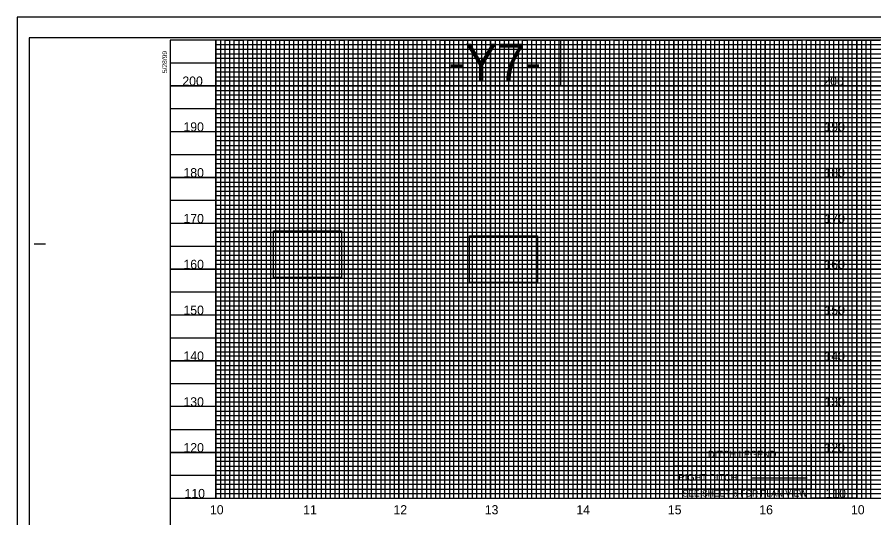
# Model space of a CAD drawing. Extents: x 1779926 to 1781626, y 618464 to 619564.
# Drawn here: x 1779926 to 1780862, y 619018 to 619564 of the extents above; entities that cross this region are included whole.
import ezdxf

# ---------------------------------------------------------------- set-up
doc = ezdxf.new("R2010")
doc.units = 0
for name, color, linetype in [('Exist Vertical Profile Horizontal Axis Label Major', 7, 'Continuous'), ('Exist Vertical Profile Vertical Axis Label', 7, 'Continuous'), ('Prop DSN Text', 7, 'Continuous'), ('Prop Grid Mask', 7, 'Continuous'), ('Prop PFL Ditch Label CELL', 7, 'Continuous'), ('Sheet DOT Grid CELL', 7, 'Continuous'), ('Sheet Layout Profile Border Port 1', 7, 'Continuous'), ('Sheet Plot Border Inside CELL', 7, 'Continuous'), ('Sheet Plot Border Outside CELL', 7, 'Continuous'), ('Sheet Profile CELL', 7, 'Continuous'), ('Sheet Profile Grid Major CELL', 7, 'Continuous'), ('Sheet Profile Grid Middle CELL', 7, 'Continuous'), ('Sheet Profile Grid Minor CELL', 7, 'Continuous')]:
    doc.layers.add(name, color=color, linetype=linetype)

msp = doc.modelspace()

# ---------------------------------------------------------------- linework, layer by layer
at = {"layer": 'Prop Grid Mask'}
for points in [[(1780519.62, 619539.19), (1780392.96, 619539.19), (1780392.96, 619489.19), (1780519.62, 619489.19)], [(1780792.96, 619539.19), (1780842.96, 619539.19), (1780842.96, 619039.19), (1780792.96, 619039.19)], [(1780205.9, 619330.88), (1780280.15, 619330.88), (1780280.15, 619279.97), (1780205.9, 619279.97)], [(1780420.08, 619325.67), (1780494.33, 619325.67), (1780494.33, 619274.76), (1780420.08, 619274.76)], [(1780642.96, 619099.19), (1780792.96, 619099.19), (1780792.96, 619074.19), (1780642.96, 619074.19)], [(1780642.96, 619074.19), (1780792.96, 619074.19), (1780792.96, 619049.19), (1780642.96, 619049.19)], [(1780792.96, 619049.19), (1780647.96, 619049.19), (1780647.96, 619039.19), (1780792.96, 619039.19)]]:
    msp.add_lwpolyline(points, close=True, dxfattribs=at)
at = {"layer": 'Prop PFL Ditch Label CELL'}
for p, q in [((1780642.96, 619059.19), (1780642.96, 619059.19)), ((1780728.51, 619061.54), (1780788.51, 619061.54)), ((1780728.51, 619061.54), (1780788.51, 619061.54))]:
    msp.add_line(p, q, dxfattribs=at)
at = {"layer": 'Sheet DOT Grid CELL'}
for p, q in [((1780142.96, 619039.19), (1780142.96, 619539.19)), ((1780192.96, 619039.19), (1780192.96, 619539.19)), ((1780242.96, 619039.19), (1780242.96, 619539.19)), ((1780292.96, 619039.19), (1780292.96, 619539.19)), ((1780342.96, 619039.19), (1780342.96, 619539.19)), ((1780392.96, 619039.19), (1780392.96, 619539.19)), ((1780442.96, 619039.19), (1780442.96, 619539.19)), ((1780492.96, 619039.19), (1780492.96, 619539.19)), ((1780542.96, 619039.19), (1780542.96, 619539.19)), ((1780592.96, 619039.19), (1780592.96, 619539.19)), ((1780642.96, 619039.19), (1780642.96, 619539.19)), ((1780692.96, 619039.19), (1780692.96, 619539.19)), ((1780742.96, 619039.19), (1780742.96, 619539.19)), ((1780792.96, 619039.19), (1780792.96, 619539.19)), ((1780842.96, 619039.19), (1780842.96, 619539.19)), ((1781392.91, 619489.19), (1780092.96, 619489.19)), ((1781392.91, 619439.19), (1780092.96, 619439.19)), ((1781392.96, 619389.19), (1780092.96, 619389.19)), ((1781392.91, 619339.19), (1780092.96, 619339.19)), ((1781592.96, 619289.19), (1780092.96, 619289.19)), ((1781592.96, 619239.19), (1780092.96, 619239.19)), ((1781592.96, 619189.19), (1780092.96, 619189.19)), ((1781592.96, 619139.19), (1780092.96, 619139.19)), ((1781592.96, 619089.19), (1780092.96, 619089.19))]:
    msp.add_line(p, q, dxfattribs=at)
at = {"layer": 'Sheet Layout Profile Border Port 1'}
for points in [[(1781542.96, 619099.19), (1781542.96, 619314.19), (1781392.91, 619314.19), (1781392.96, 619539.19), (1780142.96, 619539.19), (1780142.96, 619039.19), (1781542.96, 619039.19), (1781542.96, 619049.19)], [(1780142.96, 619378.14), (1780142.96, 619039.19), (1781542.96, 619039.19), (1781542.96, 619314.19)]]:
    msp.add_lwpolyline(points, dxfattribs=at)
at = {"layer": 'Sheet Plot Border Inside CELL'}
msp.add_lwpolyline([(1779938.96, 618486.64), (1781605.46, 618486.64), (1781605.46, 619541.74), (1779938.96, 619541.74)], close=True, dxfattribs=at)
at = {"layer": 'Sheet Plot Border Outside CELL'}
msp.add_lwpolyline([(1779925.96, 618464.19), (1781625.96, 618464.19), (1781625.96, 619564.19), (1779925.96, 619564.19)], close=True, dxfattribs=at)
at = {"layer": 'Sheet Profile CELL'}
for p, q in [((1779944.46, 619316.69), (1779956.96, 619316.69)), ((1780092.96, 619039.19), (1781592.96, 619039.19))]:
    msp.add_line(p, q, dxfattribs=at)
msp.add_lwpolyline([(1781592.96, 619539.19), (1780092.96, 619539.19), (1780092.96, 618489.19), (1781592.96, 618489.19)], close=True, dxfattribs=at)
at = {"layer": 'Sheet Profile Grid Major CELL'}
for points in [[(1780142.96, 619539.19), (1780142.96, 619039.19), (1780192.96, 619039.19), (1780192.96, 619539.19), (1780242.96, 619539.19), (1780242.96, 619039.19), (1780292.96, 619039.19), (1780292.96, 619539.19), (1780342.96, 619539.19), (1780342.96, 619039.19), (1780392.96, 619039.19), (1780392.96, 619539.19), (1780442.96, 619539.19), (1780442.96, 619039.19), (1780492.96, 619039.19), (1780492.96, 619539.19), (1780542.96, 619539.19), (1780542.96, 619039.19), (1780592.96, 619039.19), (1780592.96, 619539.19), (1780642.96, 619539.19), (1780642.96, 619039.19), (1780692.96, 619039.19), (1780692.96, 619539.19), (1780742.96, 619539.19), (1780742.96, 619039.19), (1780792.96, 619039.19), (1780792.96, 619539.19), (1780842.96, 619539.19), (1780842.96, 619039.19), (1780892.96, 619039.19)], [(1780092.96, 619489.19), (1781392.96, 619489.19)], [(1781392.96, 619439.19), (1780092.96, 619439.19), (1780092.96, 619389.19), (1781392.96, 619389.19)], [(1781392.96, 619339.19), (1780092.96, 619339.19), (1780092.96, 619289.19), (1781592.96, 619289.19)], [(1781592.96, 619239.19), (1780092.96, 619239.19), (1780092.96, 619189.19), (1781592.96, 619189.19)], [(1781592.96, 619139.19), (1780092.96, 619139.19), (1780092.96, 619139.19), (1780092.96, 619089.19), (1781592.96, 619089.19)]]:
    msp.add_lwpolyline(points, dxfattribs=at)
at = {"layer": 'Sheet Profile Grid Middle CELL'}
msp.add_line((1780092.96, 619514.19), (1781392.91, 619514.19), dxfattribs=at)
for points in [[(1780167.96, 619539.19), (1780167.96, 619039.19), (1780217.96, 619039.19), (1780217.96, 619539.19), (1780267.96, 619539.19), (1780267.96, 619039.19), (1780317.96, 619039.19), (1780317.96, 619539.19), (1780367.96, 619539.19), (1780367.96, 619039.19), (1780417.96, 619039.19), (1780417.96, 619539.19), (1780467.96, 619539.19), (1780467.96, 619039.19), (1780517.96, 619039.19), (1780517.96, 619539.19), (1780567.96, 619539.19), (1780567.96, 619039.19), (1780617.96, 619039.19), (1780617.96, 619539.19), (1780667.96, 619539.19), (1780667.96, 619039.19), (1780717.96, 619039.19), (1780717.96, 619039.19), (1780717.96, 619539.19), (1780767.96, 619539.19), (1780767.96, 619039.19), (1780817.96, 619039.19), (1780817.96, 619539.19), (1780867.96, 619539.19)], [(1781392.96, 619464.19), (1780092.96, 619464.19), (1780092.96, 619414.19), (1781392.96, 619414.19)], [(1781392.91, 619364.19), (1780092.96, 619364.19), (1780092.96, 619314.19), (1781417.96, 619314.19)], [(1781592.96, 619264.19), (1780092.96, 619264.19), (1780092.96, 619214.19), (1781592.96, 619214.19)], [(1781592.96, 619164.19), (1780092.96, 619164.19), (1780092.96, 619114.19), (1781592.96, 619114.19)], [(1781592.96, 619064.19), (1780092.96, 619064.19)]]:
    msp.add_lwpolyline(points, dxfattribs=at)
at = {"layer": 'Sheet Profile Grid Minor CELL'}
for p, q in [((1780142.96, 619534.19), (1781392.96, 619534.19)), ((1780142.96, 619529.19), (1780142.96, 619529.19)), ((1781392.96, 619529.19), (1780142.96, 619528.84)), ((1780142.96, 619524.19), (1781392.96, 619524.19)), ((1781392.91, 619404.19), (1780142.96, 619404.19)), ((1781392.96, 619399.19), (1780142.96, 619399.19)), ((1781392.96, 619394.19), (1780142.96, 619394.19)), ((1780142.96, 619384.19), (1781392.96, 619384.19)), ((1781392.96, 619379.19), (1780142.96, 619379.19)), ((1780142.96, 619374.19), (1781392.91, 619374.19)), ((1781392.91, 619354.19), (1780142.96, 619354.19)), ((1780142.96, 619349.19), (1781392.91, 619349.19)), ((1781392.91, 619329.19), (1780142.96, 619329.19)), ((1780142.96, 619324.19), (1781392.91, 619324.19)), ((1781542.96, 619304.19), (1780142.96, 619304.19)), ((1780142.96, 619299.19), (1781542.96, 619299.19)), ((1781542.96, 619294.19), (1780142.96, 619294.19)), ((1780142.96, 619284.19), (1781542.96, 619284.19)), ((1781542.96, 619279.19), (1780142.96, 619279.19)), ((1780142.96, 619274.19), (1781542.96, 619274.19)), ((1781542.96, 619269.19), (1780142.96, 619269.19)), ((1780142.96, 619259.19), (1781542.96, 619259.19)), ((1781542.96, 619254.19), (1780142.96, 619254.19)), ((1780142.96, 619249.19), (1781542.96, 619249.19)), ((1781542.96, 619244.19), (1780142.96, 619244.19)), ((1780142.96, 619234.19), (1781542.96, 619234.19)), ((1781542.96, 619229.19), (1780142.96, 619229.19)), ((1780142.96, 619224.19), (1781542.96, 619224.19)), ((1781542.96, 619219.19), (1780142.96, 619219.19)), ((1780142.96, 619209.19), (1781542.96, 619209.19)), ((1781542.96, 619204.19), (1780142.96, 619204.19)), ((1780142.96, 619199.19), (1781542.96, 619199.19)), ((1781542.96, 619194.19), (1780142.96, 619194.19)), ((1780142.96, 619184.19), (1781542.96, 619184.19)), ((1781542.96, 619179.19), (1780142.96, 619179.19)), ((1780142.96, 619174.19), (1781542.96, 619174.19)), ((1781542.96, 619169.19), (1780142.96, 619169.19)), ((1780142.96, 619159.19), (1781542.96, 619159.19)), ((1781542.96, 619154.19), (1780142.96, 619154.19)), ((1781542.96, 619149.19), (1780142.96, 619149.19)), ((1781542.96, 619144.19), (1780142.96, 619144.19)), ((1780142.96, 619134.19), (1781542.96, 619134.19)), ((1781542.96, 619129.19), (1780142.96, 619129.19)), ((1780142.96, 619124.19), (1781542.96, 619124.19)), ((1781542.96, 619119.19), (1780142.96, 619119.19)), ((1780142.96, 619109.19), (1781542.96, 619109.19)), ((1781542.96, 619104.19), (1780142.96, 619104.19)), ((1780142.96, 619099.19), (1781542.96, 619099.19)), ((1781542.96, 619094.19), (1780142.96, 619094.19)), ((1780142.96, 619084.19), (1781542.96, 619084.19)), ((1781542.96, 619079.19), (1780142.96, 619079.19)), ((1780142.96, 619074.19), (1781542.96, 619074.19)), ((1781542.96, 619069.19), (1780142.96, 619069.19)), ((1780142.96, 619059.19), (1781542.96, 619059.19)), ((1781542.96, 619054.19), (1780142.96, 619054.19)), ((1780142.96, 619049.19), (1781542.96, 619049.19))]:
    msp.add_line(p, q, dxfattribs=at)
for points in [[(1780147.96, 619539.19), (1780147.96, 619039.19), (1780152.96, 619039.19), (1780152.96, 619539.19), (1780157.96, 619539.19), (1780157.96, 619039.19), (1780162.96, 619039.19), (1780162.96, 619539.19), (1780172.96, 619539.19), (1780172.96, 619039.19), (1780177.96, 619039.19), (1780177.96, 619539.19), (1780182.96, 619539.19), (1780182.96, 619039.19), (1780187.96, 619039.19), (1780197.96, 619039.19), (1780202.96, 619039.19), (1780202.96, 619539.19), (1780207.96, 619539.19), (1780207.96, 619039.19), (1780212.96, 619039.19), (1780212.96, 619539.19), (1780222.96, 619539.19), (1780222.96, 619039.19), (1780227.96, 619039.19), (1780227.96, 619539.19), (1780232.96, 619539.19), (1780232.96, 619039.19), (1780237.96, 619039.19), (1780237.96, 619539.19), (1780247.96, 619539.19), (1780247.96, 619039.19), (1780252.96, 619039.19), (1780252.96, 619539.19), (1780257.96, 619539.19), (1780257.96, 619039.19), (1780262.96, 619039.19), (1780262.96, 619539.19), (1780272.96, 619539.19), (1780272.96, 619039.19), (1780277.96, 619039.19), (1780277.96, 619539.19), (1780282.96, 619539.19), (1780282.96, 619039.19), (1780287.96, 619039.19), (1780287.96, 619539.19), (1780297.96, 619539.19), (1780297.96, 619039.19), (1780302.96, 619039.19), (1780302.96, 619539.19), (1780307.96, 619539.19), (1780307.96, 619039.19), (1780312.96, 619039.19), (1780312.96, 619539.19), (1780322.96, 619539.19), (1780322.96, 619039.19), (1780327.96, 619039.19), (1780327.96, 619539.19), (1780332.96, 619539.19), (1780332.96, 619039.19), (1780337.96, 619039.19), (1780337.96, 619539.19), (1780347.96, 619539.19), (1780347.96, 619039.19), (1780352.96, 619039.19), (1780352.96, 619539.19), (1780357.96, 619539.19), (1780357.96, 619039.19)], [(1780187.96, 619039.19), (1780187.96, 619539.19), (1780197.96, 619539.19), (1780197.96, 619039.19)], [(1780357.96, 619039.19), (1780362.96, 619039.19), (1780362.96, 619539.19), (1780372.96, 619539.19), (1780372.96, 619039.19), (1780377.96, 619039.19), (1780377.96, 619539.19), (1780382.96, 619539.19), (1780382.96, 619039.19), (1780387.96, 619039.19), (1780387.96, 619539.19), (1780397.96, 619539.19), (1780397.96, 619039.19), (1780402.96, 619039.19), (1780402.96, 619539.19), (1780407.96, 619539.19), (1780407.96, 619039.19), (1780412.96, 619039.19), (1780412.96, 619539.19), (1780422.96, 619539.19), (1780422.96, 619039.19), (1780427.96, 619039.19), (1780427.96, 619539.19), (1780432.96, 619539.19), (1780432.96, 619039.19), (1780437.96, 619039.19), (1780437.96, 619539.19), (1780447.96, 619539.19), (1780447.96, 619039.19), (1780452.96, 619039.19), (1780452.96, 619539.19), (1780457.96, 619539.19), (1780457.96, 619039.19), (1780462.96, 619039.19), (1780462.96, 619539.19), (1780472.96, 619539.19), (1780472.96, 619039.19), (1780477.96, 619039.19), (1780477.96, 619539.19), (1780482.96, 619539.19), (1780482.96, 619039.19), (1780487.96, 619039.19), (1780487.96, 619539.19), (1780497.96, 619539.19), (1780497.96, 619039.19), (1780502.96, 619039.19), (1780502.96, 619539.19), (1780507.96, 619539.19), (1780507.96, 619039.19), (1780512.96, 619039.19), (1780512.96, 619539.19), (1780522.96, 619539.19), (1780522.96, 619039.19), (1780527.96, 619039.19), (1780527.96, 619539.19), (1780532.96, 619539.19), (1780532.96, 619039.19), (1780537.96, 619039.19), (1780537.96, 619539.19), (1780547.96, 619539.19), (1780547.96, 619039.19), (1780552.96, 619039.19), (1780552.96, 619539.19), (1780557.96, 619539.19), (1780557.96, 619039.19), (1780562.96, 619039.19), (1780562.96, 619539.19), (1780572.96, 619539.19), (1780572.96, 619039.19), (1780577.96, 619039.19), (1780577.96, 619539.19), (1780582.96, 619539.19), (1780582.96, 619039.19), (1780587.96, 619039.19), (1780587.96, 619539.19), (1780597.96, 619539.19), (1780597.96, 619039.19), (1780602.96, 619039.19), (1780602.96, 619539.19), (1780607.96, 619539.19), (1780607.96, 619039.19), (1780612.96, 619039.19), (1780612.96, 619539.19), (1780622.96, 619539.19), (1780622.96, 619039.19), (1780627.96, 619039.19), (1780627.96, 619539.19), (1780632.96, 619539.19), (1780632.96, 619039.19), (1780637.96, 619039.19), (1780637.96, 619539.19), (1780647.96, 619539.19), (1780647.96, 619039.19), (1780652.96, 619039.19), (1780652.96, 619539.19), (1780657.96, 619539.19), (1780657.96, 619039.19), (1780662.96, 619039.19), (1780662.96, 619539.19), (1780672.96, 619539.19)], [(1780672.96, 619539.19), (1780672.96, 619039.19), (1780677.96, 619039.19), (1780677.96, 619539.19), (1780682.96, 619539.19), (1780682.96, 619039.19), (1780687.96, 619039.19), (1780687.96, 619539.19), (1780697.96, 619539.19), (1780697.96, 619039.19), (1780702.96, 619039.19), (1780702.96, 619539.19), (1780707.96, 619539.19), (1780707.96, 619039.19), (1780712.96, 619039.19), (1780712.96, 619539.19), (1780722.96, 619539.19), (1780722.96, 619039.19), (1780727.96, 619039.19), (1780727.96, 619539.19), (1780732.96, 619539.19), (1780732.96, 619039.19), (1780737.96, 619039.19), (1780737.96, 619539.19), (1780747.96, 619539.19), (1780747.96, 619039.19), (1780752.96, 619039.19), (1780752.96, 619539.19), (1780757.96, 619539.19), (1780757.96, 619039.19), (1780762.96, 619039.19), (1780762.96, 619539.19), (1780772.96, 619539.19), (1780772.96, 619039.19), (1780777.96, 619039.19), (1780777.96, 619539.19), (1780782.96, 619539.19), (1780782.96, 619039.19), (1780787.96, 619039.19), (1780787.96, 619539.19), (1780797.96, 619539.19), (1780797.96, 619039.19), (1780797.96, 619039.19), (1780802.96, 619039.19), (1780802.96, 619539.19), (1780807.96, 619539.19), (1780807.96, 619039.19), (1780812.96, 619039.19), (1780812.96, 619539.19), (1780822.96, 619539.19), (1780822.96, 619039.19), (1780827.96, 619039.19), (1780827.96, 619539.19), (1780832.96, 619539.19), (1780832.96, 619039.19), (1780837.96, 619039.19), (1780837.96, 619539.19), (1780847.96, 619539.19), (1780847.96, 619039.19), (1780852.96, 619039.19), (1780852.96, 619539.19), (1780857.96, 619539.19), (1780857.96, 619039.19), (1780862.96, 619039.19)], [(1781392.96, 619519.19), (1780142.96, 619519.19), (1780142.96, 619509.19), (1781392.96, 619509.19)], [(1781392.91, 619504.19), (1780142.96, 619504.19), (1780142.96, 619499.19), (1781392.96, 619499.19)], [(1781392.96, 619494.19), (1780142.96, 619494.19), (1780142.96, 619484.19), (1781392.96, 619484.19)], [(1781392.96, 619479.19), (1780142.96, 619479.19), (1780142.96, 619474.19), (1781392.96, 619474.19)], [(1781392.96, 619469.19), (1780142.96, 619469.19), (1780142.96, 619459.19), (1781392.96, 619459.19)], [(1781392.96, 619454.19), (1780142.96, 619454.19), (1780142.96, 619449.19), (1781392.96, 619449.19)], [(1781392.96, 619444.19), (1780142.96, 619444.19), (1780142.96, 619434.19), (1781392.96, 619434.19)], [(1781392.96, 619429.09), (1780143.06, 619429.09), (1780143.06, 619424.19), (1781392.96, 619424.19)], [(1781392.96, 619419.19), (1780142.96, 619419.19), (1780142.96, 619409.19), (1781392.96, 619409.19)], [(1781392.91, 619369.19), (1780142.96, 619369.19), (1780142.96, 619359.19), (1781392.91, 619359.19)], [(1781392.91, 619344.19), (1780142.96, 619344.19), (1780142.96, 619334.19), (1781392.91, 619334.19)], [(1781392.91, 619319.19), (1780142.96, 619319.19), (1780142.96, 619309.19), (1781542.96, 619309.19)], [(1781542.96, 619044.19), (1780142.96, 619044.19)]]:
    msp.add_lwpolyline(points, dxfattribs=at)

# ---------------------------------------------------------------- texts
at = {"layer": 'Exist Vertical Profile Horizontal Axis Label Major'}
for s, p in [('10', (1780136.54, 619021.69)), ('11', (1780238.38, 619021.69)), ('12', (1780336.93, 619021.69)), ('13', (1780436.61, 619021.69)), ('14', (1780536.66, 619021.69)), ('15', (1780636.59, 619021.69)), ('16', (1780736.42, 619021.69)), ('10', (1780836.54, 619021.69))]:
    msp.add_text(s, height=10, dxfattribs=at).set_placement(p)
at = {"layer": 'Exist Vertical Profile Vertical Axis Label'}
for s, p in [('200', (1780106.39, 619489.44)), ('200', (1780806.39, 619489.44)), ('190', (1780107.59, 619439.44)), ('190', (1780807.59, 619439.44)), ('180', (1780107.59, 619389.44)), ('180', (1780807.59, 619389.44)), ('170', (1780107.59, 619339.44)), ('170', (1780807.59, 619339.44)), ('160', (1780107.59, 619289.44)), ('160', (1780807.59, 619289.44)), ('150', (1780107.59, 619239.44)), ('150', (1780807.59, 619239.44)), ('140', (1780107.59, 619189.44)), ('140', (1780807.59, 619189.44)), ('130', (1780107.59, 619139.44)), ('130', (1780807.59, 619139.44)), ('120', (1780107.59, 619089.44)), ('120', (1780807.59, 619089.44)), ('110', (1780108.79, 619039.44)), ('110', (1780808.79, 619039.44))]:
    msp.add_text(s, height=10, dxfattribs=at).set_placement(p)
at = {"layer": 'Prop DSN Text'}
for s, height, p in [('-Y7-', 40, (1780397.01, 619495.14)), ('SEE SHEET 6 FOR PLAN VIEW', 7, (1780652.54, 619041.14))]:
    msp.add_text(s, height=height, dxfattribs=at).set_placement(p)
at = {"layer": 'Prop PFL Ditch Label CELL'}
for s, height, p in [('DITCH LEGEND', 7.5, (1780680.46, 619083.54)), ('RIGHT DITCH', 7.485, (1780647.96, 619058.29))]:
    msp.add_text(s, height=height, dxfattribs=at).set_placement(p)
at = {"layer": 'Sheet Profile CELL'}
msp.add_text('5/28/99', height=5.25, rotation=90, dxfattribs=at).set_placement((1780089.72, 619503.1))

doc.saveas('drawing.dxf')
